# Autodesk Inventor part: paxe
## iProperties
Shininess: 21.0
Compacted: True
Length Units: 11269
Angle Units: 11279
Time Units: 11290
Mass Units: 11283
Length Display Precision: 3
Angle Display Precision: 2
Created: 2001-12
Part Number: paxe
Material: Par défaut
Document SubType Name: Modélisation
Designer: pichon
Density: 0.0
Volumn: 0.0
Area: 0.0
PropertySet Name: Model Information
Control State: 0
Master: False
Checked Out: False
Author: pichon
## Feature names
1. Révolution1 [Revolution]
